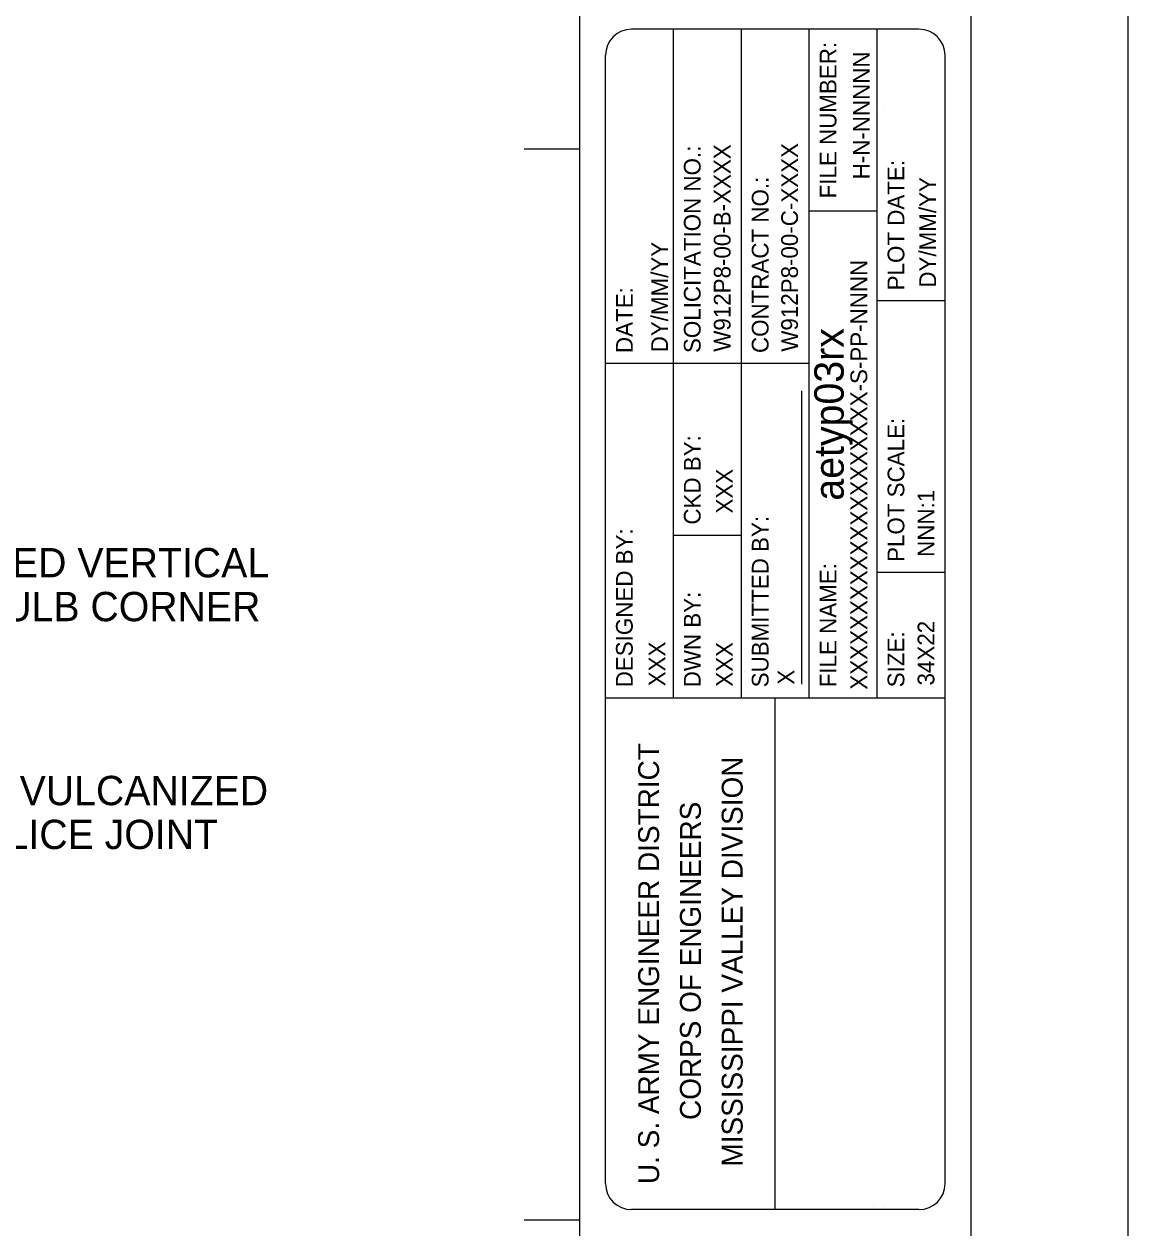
# Model space of a CAD drawing. Extents: x 22371.58 to 22374.41, y 22370.57 to 22372.4.
# Drawn here: x 22373.9714 to 22374.4116, y 22371.0559 to 22371.5361 of the extents above; entities that cross this region are included whole.
import ezdxf

# ---------------------------------------------------------------- set-up
doc = ezdxf.new("R2010")
doc.units = 0
for name, color, linetype in [('G-ANNO-SYMB', 7, 'Continuous'), ('G-ANNO-TEXT', 7, 'Continuous'), ('G-ANNO-TTBL', 7, 'Continuous'), ('G-ANNO-TTLB', 7, 'Continuous'), ('Level 10', 7, 'Continuous'), ('S-ANNO-DIMS', 7, 'Continuous'), ('S-ANNO-TEXT', 7, 'Continuous')]:
    doc.layers.add(name, color=color, linetype=linetype)

msp = doc.modelspace()

# ---------------------------------------------------------------- linework, layer by layer
at = {"layer": 'G-ANNO-SYMB'}
msp.add_lwpolyline([(22371.57831, 22372.40278), (22374.41164, 22372.40278), (22374.41164, 22370.56945), (22371.57831, 22370.56945)], close=True, dxfattribs=at)
at = {"layer": 'G-ANNO-TTBL'}
for p, q in [((22374.23039, 22371.26736), (22374.23039, 22371.53403)), ((22374.25747, 22371.26736), (22374.25747, 22371.53403)), ((22374.28456, 22371.26736), (22374.28456, 22371.53403)), ((22374.31164, 22371.26736), (22374.31164, 22371.53403)), ((22374.20331, 22371.07361), (22374.20331, 22371.52361)), ((22374.19289, 22371.48611), (22374.1709, 22371.48611)), ((22374.31164, 22371.46147), (22374.28456, 22371.46147)), ((22374.33872, 22371.4257), (22374.31164, 22371.4257)), ((22374.23051, 22371.4007), (22374.20331, 22371.4007)), ((22374.25759, 22371.4007), (22374.23039, 22371.4007)), ((22374.28456, 22371.4007), (22374.25747, 22371.4007)), ((22374.23039, 22371.33226), (22374.25759, 22371.33226)), ((22374.33872, 22371.31736), (22374.31164, 22371.31736)), ((22374.20331, 22371.26736), (22374.33872, 22371.26736)), ((22374.27101, 22371.0632), (22374.27101, 22371.26736)), ((22374.19289, 22371.05903), (22374.1709, 22371.05903))]:
    msp.add_line(p, q, dxfattribs=at)
for points in [[(22371.77622, 22372.34028), (22374.19289, 22372.34028), (22374.19289, 22370.63195), (22371.77622, 22370.63195)], [(22371.77622, 22372.34028), (22374.19289, 22372.34028), (22374.19289, 22370.63195), (22371.77622, 22370.63195)], [(22374.19289, 22370.63195), (22374.34914, 22370.63195), (22374.34914, 22372.34028), (22374.19289, 22372.34028)]]:
    msp.add_lwpolyline(points, close=True, dxfattribs=at)
for points in [[(22374.32831, 22371.53403), (22374.21372, 22371.53403)], [(22374.33872, 22371.07361), (22374.33872, 22371.52361)], [(22374.32831, 22371.0632), (22374.21372, 22371.0632)]]:
    msp.add_lwpolyline(points, dxfattribs=at)
for centre, start, end in [((22374.21372, 22371.52361), 90, 180), ((22374.32831, 22371.52361), 0, 90), ((22374.21372, 22371.07361), 180, 270), ((22374.32831, 22371.07361), 270, 0)]:
    msp.add_arc(centre, 0.01042, start, end, dxfattribs=at)
at = {"layer": 'G-ANNO-TTLB'}
msp.add_line((22374.28163, 22371.27275), (22374.28163, 22371.38975), dxfattribs=at)
at = {"layer": 'S-ANNO-DIMS'}
for p, q in [((22374.31002, 22371.50331), (22374.31002, 22371.50331)), ((22374.31436, 22371.50331), (22374.31436, 22371.50331)), ((22374.20325, 22371.27784), (22374.20325, 22371.27784)), ((22374.20759, 22371.27784), (22374.20759, 22371.27784)), ((22374.25446, 22371.27784), (22374.25446, 22371.27784)), ((22374.25879, 22371.27784), (22374.25879, 22371.27784)), ((22374.23536, 22371.10597), (22374.23536, 22371.10597)), ((22374.31002, 22371.0643), (22374.31002, 22371.0643)), ((22374.31436, 22371.0643), (22374.31436, 22371.0643))]:
    msp.add_line(p, q, dxfattribs=at)

# ---------------------------------------------------------------- texts
at = {"layer": 'G-ANNO-TEXT'}
for s, height, p in [('FILE NUMBER:', 0.0066667, (22374.29539, 22371.46655)), ('SOLICITATION NO.:', 0.0066667, (22374.24122, 22371.40486)), ('PLOT DATE:', 0.006667, (22374.32247, 22371.42986)), ('CONTRACT NO.:', 0.0066667, (22374.26831, 22371.40486)), ('DATE:', 0.006667, (22374.21415, 22371.40486)), ('PLOT SCALE:', 0.0066667, (22374.32247, 22371.32153)), ('CKD BY:', 0.006667, (22374.24122, 22371.33643)), ('SUBMITTED BY:', 0.0066667, (22374.26831, 22371.27153)), ('DESIGNED BY:', 0.0066667, (22374.21415, 22371.27153)), ('FILE NAME:', 0.006667, (22374.29539, 22371.27153)), ('DWN BY:', 0.006667, (22374.24122, 22371.27153)), ('SIZE:', 0.006667, (22374.32247, 22371.27153)), ('U. S. ARMY ENGINEER DISTRICT', 0.0083333, (22374.22466, 22371.07341)), ('MISSISSIPPI VALLEY DIVISION', 0.0083333, (22374.25799, 22371.0804)), ('CORPS OF ENGINEERS', 0.0083333, (22374.24133, 22371.09896))]:
    msp.add_text(s, height=height, rotation=90, dxfattribs=at).set_placement(p)
at = {"layer": 'G-ANNO-TTLB'}
for s, height, p in [('H-N-NNNNN', 0.006667, (22374.30868, 22371.47413)), ('W912P8-00-B-XXXX', 0.0066667, (22374.25316, 22371.40538)), ('W912P8-00-C-XXXX', 0.0066667, (22374.28004, 22371.40539)), ('DY/MM/YY', 0.006667, (22374.33512, 22371.43094)), ('DY/MM/YY', 0.006667, (22374.22819, 22371.40514)), ('XXXXXXXXXXXXXXXXXXXX-S-PP-NNNN', 0.0066667, (22374.30766, 22371.27061)), ('XXX', 0.006667, (22374.25406, 22371.34085)), ('NNN:1', 0.006667, (22374.33444, 22371.32356)), ('34X22', 0.006667, (22374.33444, 22371.27227)), ('XXX', 0.006667, (22374.22715, 22371.27193)), ('XXX', 0.006667, (22374.25407, 22371.27176)), ('X', 0.00667, (22374.27861, 22371.27259))]:
    msp.add_text(s, height=height, rotation=90, dxfattribs=at).set_placement(p)
at = {"layer": 'Level 10'}
msp.add_text('aetyp03rx', height=0.011719, rotation=90, dxfattribs=at).set_placement((22374.29829, 22371.34597))
at = {"layer": 'S-ANNO-TEXT'}
for s, p in [('FULL MOLDED VERTICAL', (22373.8788, 22371.31539)), ('OUTSIDE BULB CORNER', (22373.8788, 22371.29789)), ('FACTORY VULCANIZED', (22373.89057, 22371.22452)), ('MITER SPLICE JOINT', (22373.89057, 22371.20702))]:
    msp.add_text(s, height=0.0116979, dxfattribs=at).set_placement(p)

doc.saveas('drawing.dxf')
